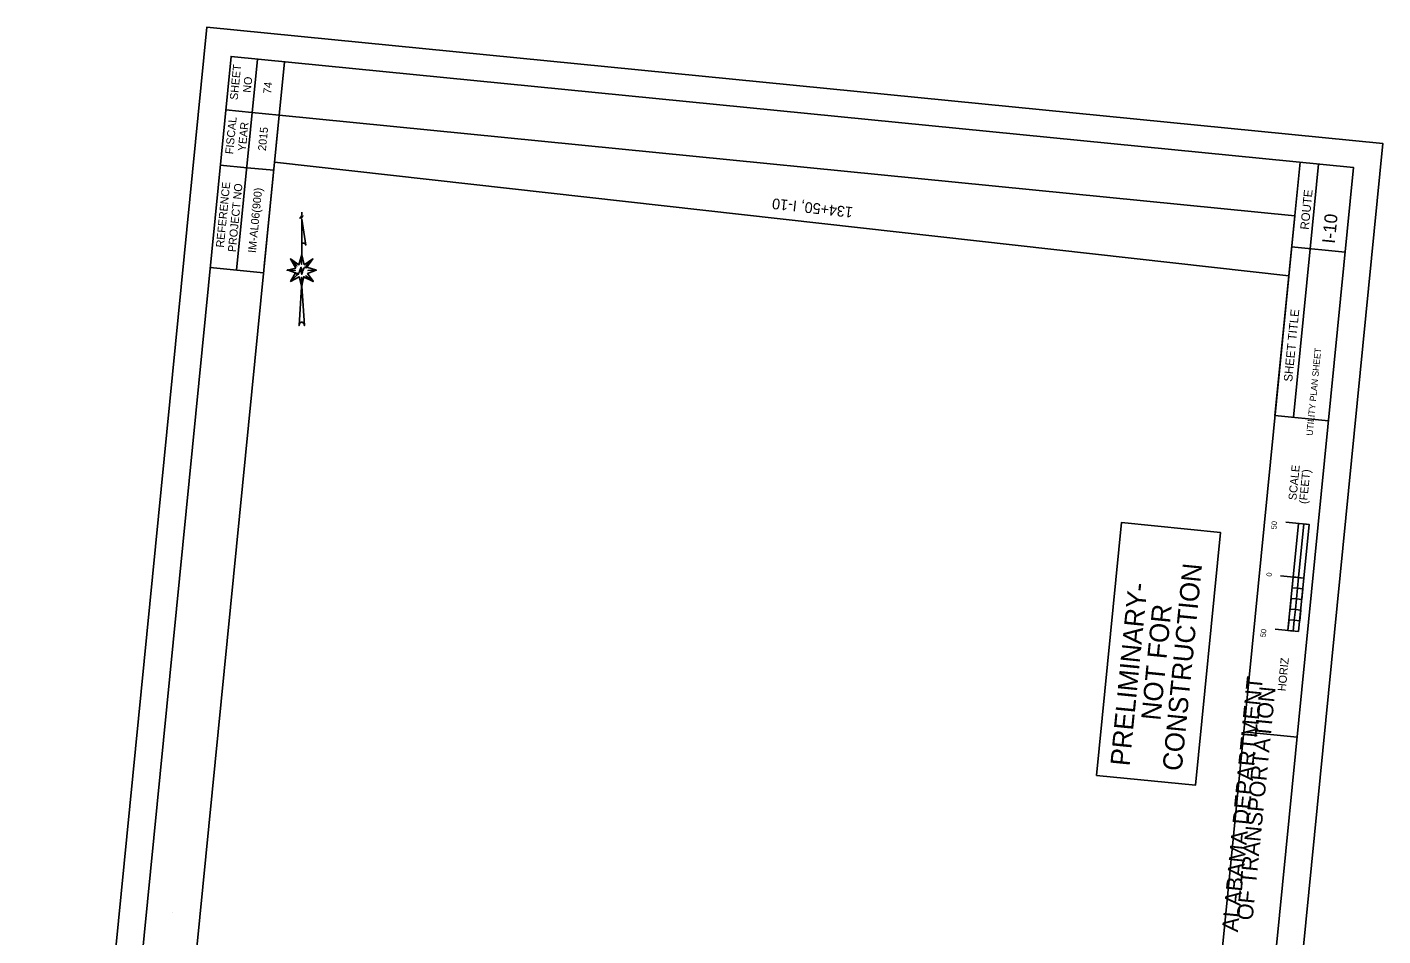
# Model space of a CAD drawing. Extents: x 1797076 to 1798338, y 246730 to 248530.
# Drawn here: x 1797076 to 1798338, y 247685 to 248530 of the extents above; entities that cross this region are included whole.
import ezdxf

# ---------------------------------------------------------------- set-up
doc = ezdxf.new("R2010")
doc.units = 0
for name, color, linetype in [('1', 7, 'Continuous'), ('29', 7, 'Continuous'), ('ANNO-SHT', 7, 'Continuous'), ('ANNO-SYMB', 7, 'Continuous'), ('ANNO-TXT', 7, 'Continuous'), ('DRAINAGE', 7, 'Continuous'), ('Level 1', 7, 'Continuous'), ('Level 57', 7, 'Continuous'), ('Level 6', 7, 'Continuous'), ('Level 62', 7, 'Continuous'), ('SHT-BDR', 7, 'Continuous'), ('SHT-BNDRY', 7, 'Continuous')]:
    doc.layers.add(name, color=color, linetype=linetype)

# ---------------------------------------------------------------- blocks, each defined once
blk = doc.blocks.new('SC47208')
at = {"layer": 'Level 1'}
blk.add_line((0, 0), (0, 0), dxfattribs=at)

msp = doc.modelspace()

# ---------------------------------------------------------------- linework, layer by layer
at = {"layer": '1'}
msp.add_lwpolyline([(1798071.6, 247833.9), (1798094.8, 248069.2), (1798187, 248060.1), (1798163.7, 247824.8)], close=True, dxfattribs=at)
at = {"layer": '29'}
msp.add_line((1797306.5, 248404.6), (1798250.6, 248298.9), dxfattribs=at)
at = {"layer": 'ANNO-SYMB'}
for p, q in [((1798269.7, 248067.4), (1798247.8, 248069.5)), ((1798259.7, 248068.3), (1798249.9, 247968.8)), ((1798269.7, 248067.4), (1798259.8, 247967.8)), ((1798269.7, 248067.4), (1798264.7, 248067.9)), ((1798269.7, 248067.4), (1798264.7, 248067.9)), ((1798269.7, 248067.4), (1798264.7, 248067.9)), ((1798264.7, 248017.6), (1798242.9, 248019.8)), ((1798264.7, 248017.6), (1798242.9, 248019.8)), ((1798264.7, 248017.6), (1798242.9, 248019.8)), ((1798259.8, 248018.1), (1798254.8, 248018.6)), ((1798259.8, 248018.1), (1798254.8, 248018.6)), ((1798259.8, 248018.1), (1798254.8, 248018.6)), ((1798259.8, 248018.1), (1798257.8, 247998.2)), ((1798259.8, 247967.8), (1798237.9, 247970)), ((1798255.8, 247978.3), (1798250.9, 247978.8)), ((1798255.8, 247978.3), (1798250.9, 247978.8))]:
    msp.add_line(p, q, dxfattribs=at)
for points in [[(1798259.8, 248018.1), (1798264.7, 248067.9), (1798269.7, 248067.4), (1798264.7, 248017.6)], [(1798253.8, 248008.6), (1798254.8, 248018.6), (1798259.8, 248018.1), (1798258.8, 248008.1)], [(1798257.8, 247998.2), (1798258.8, 248008.1), (1798263.8, 248007.7), (1798262.8, 247997.7)], [(1798251.8, 247988.7), (1798252.8, 247998.7), (1798257.8, 247998.2), (1798256.8, 247988.2)], [(1798255.8, 247978.3), (1798256.8, 247988.2), (1798261.8, 247987.7), (1798260.8, 247977.8)], [(1798249.9, 247968.8), (1798250.9, 247978.8), (1798255.8, 247978.3), (1798254.8, 247968.3)]]:
    msp.add_lwpolyline(points, close=True, dxfattribs=at)
at = {"layer": 'ANNO-TXT'}
for p, q in [((1798270.6, 248324.1), (1798278.4, 248402.8)), ((1798255.1, 248167.3), (1798270.6, 248324.1))]:
    msp.add_line(p, q, dxfattribs=at)
at = {"layer": 'Level 57'}
msp.add_line((1797331.9, 248358.2), (1797331.8, 248355.7), dxfattribs=at)
for points in [[(1797333, 248354.6), (1797332.9, 248354.6), (1797333, 248354.4), (1797333.1, 248354.6), (1797333, 248354.7), (1797332.8, 248354.7), (1797332.6, 248354.6), (1797332.4, 248354.5), (1797332.2, 248354.1), (1797332.1, 248353.7), (1797331.9, 248353.1), (1797331.8, 248353), (1797331.7, 248352.6), (1797331.7, 248353.2), (1797331.7, 248354.1), (1797331.5, 248354.7), (1797331.5, 248354.1), (1797331.7, 248352.6), (1797331.7, 248354.1), (1797331.5, 248354.7), (1797331.3, 248354.2), (1797330.9, 248353.1), (1797330.6, 248352.6), (1797330.4, 248352.5), (1797330.2, 248352.5), (1797330.1, 248352.6), (1797330.1, 248352.8), (1797330.2, 248352.9), (1797330.3, 248352.8), (1797330.2, 248352.7)], [(1797331.8, 248351.6), (1797335.5, 248327.5), (1797335.3, 248328.3), (1797335.1, 248328.6), (1797334.7, 248328.9), (1797334.2, 248329.2), (1797333.9, 248329.2), (1797333.5, 248329.2), (1797333.1, 248329.3), (1797332.8, 248329.1), (1797332.5, 248329), (1797332.2, 248328.7), (1797332, 248328.5), (1797331.9, 248328.2), (1797331.8, 248328), (1797331.8, 248351.5), (1797331.9, 248318.6)], [(1797331.9, 248318.6), (1797331.7, 248309.7), (1797331.9, 248318.7), (1797329.2, 248309.1), (1797321.3, 248314.6), (1797327.4, 248307.9), (1797321.3, 248314.6), (1797326.2, 248306.1), (1797318.2, 248304.1), (1797325.9, 248303.9), (1797318.3, 248304.3), (1797326.1, 248301.5), (1797321.5, 248293.6), (1797327.3, 248299.4), (1797321.5, 248293.6), (1797329.4, 248298), (1797331.7, 248289.1), (1797331.6, 248297.4), (1797331.7, 248288.9), (1797333.7, 248297.9), (1797342.7, 248293.7), (1797333.6, 248297.9), (1797331.7, 248288.6), (1797329.4, 248252.6), (1797329.6, 248253.8), (1797329.9, 248254.6), (1797330.4, 248255.1), (1797331, 248255.5), (1797331.5, 248255.6), (1797332.2, 248255.6), (1797332.7, 248255.4), (1797333.2, 248255.1), (1797333.6, 248254.6), (1797334, 248254), (1797334.1, 248253.5), (1797334.3, 248252.6), (1797331.8, 248289.1), (1797333.6, 248298), (1797342.5, 248293.7), (1797335.7, 248299), (1797342.4, 248293.9), (1797337.2, 248300.9), (1797345.2, 248304), (1797337.6, 248303.9), (1797345.5, 248304), (1797336.7, 248306.8), (1797342.2, 248314.6), (1797335.7, 248308.3), (1797342.2, 248314.6), (1797334.2, 248309.1), (1797332, 248318.5)], [(1797335.7, 248306.6), (1797335.5, 248306.4), (1797335.8, 248306.1), (1797336, 248306.5), (1797335.9, 248306.8), (1797335.8, 248307), (1797335.1, 248306.9), (1797334.5, 248306.6), (1797333.5, 248305.4), (1797333.4, 248304.9), (1797333, 248303.7), (1797332.6, 248302.5), (1797332.1, 248301.6), (1797331.9, 248300.2), (1797331.9, 248302), (1797331.7, 248304.2), (1797331.6, 248305.4), (1797331.1, 248306.8), (1797331.1, 248305.1), (1797331.4, 248302.9), (1797331.6, 248301.4), (1797331.9, 248300.3), (1797331.9, 248302.3), (1797331.7, 248305.4), (1797331.1, 248306.9), (1797330.8, 248305.4), (1797330.2, 248303.8), (1797329.9, 248303.1), (1797329.6, 248302.3), (1797329.2, 248301.5), (1797328.9, 248301), (1797328.7, 248300.4), (1797327.8, 248300.1), (1797327.2, 248300.2), (1797327, 248300.5), (1797326.9, 248301.2), (1797327.3, 248301.5), (1797327.6, 248301.1), (1797327.4, 248300.9)]]:
    msp.add_lwpolyline(points, dxfattribs=at)
at = {"layer": 'Level 6'}
for p, q in [((1797290.6, 248500.6), (1797271.2, 248304.2)), ((1797315.7, 248498.1), (1797296.9, 248307.8)), ((1797285.3, 248450.8), (1797261.1, 248453.2)), ((1797285.3, 248450.8), (1797310.8, 248448.3)), ((1797280.9, 248399.5), (1797256, 248402)), ((1797280.9, 248399.5), (1797305.7, 248397.1)), ((1798261.1, 248404.5), (1798237.8, 248169)), ((1797246.6, 248306.7), (1797296.3, 248301.7))]:
    msp.add_line(p, q, dxfattribs=at)
at = {"layer": 'Level 62'}
msp.add_lwpolyline([(1798170.8, 246730.3), (1798338.2, 248422), (1797243.6, 248530.3), (1797076.2, 246838.6)], close=True, dxfattribs=at)
at = {"layer": 'SHT-BDR'}
msp.add_lwpolyline([(1798108.5, 246862), (1798256.2, 248354.7), (1797310.8, 248448.3), (1797163.1, 246955.6)], close=True, dxfattribs=at)
at = {"layer": 'SHT-BNDRY'}
for p, q in [((1798303.1, 248320.9), (1798253.3, 248325.8)), ((1798287.6, 248164), (1798237.8, 248169)), ((1798258.5, 247869.5), (1798208.6, 247874.5))]:
    msp.add_line(p, q, dxfattribs=at)
msp.add_lwpolyline([(1798152.1, 246794.9), (1798310.9, 248399.6), (1797266, 248503), (1797107.2, 246898.3)], close=True, dxfattribs=at)

# ---------------------------------------------------------------- block references
at = {"layer": 'DRAINAGE', "xscale": 1.000002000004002, "yscale": 1.000002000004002, "rotation": -32.06753455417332}
msp.add_blockref('SC47208', (1797211.3, 247706.1), dxfattribs=at)
msp.add_blockref('SC47208', (1797211.3, 247706.1), dxfattribs=at)

# ---------------------------------------------------------------- texts
at = {"layer": '1'}
for s, p in [('CONSTRUCTION', (1798150.9, 247837.4)), ('PRELIMINARY-', (1798102.4, 247842.1)), ('NOT FOR', (1798131.1, 247884.5))]:
    msp.add_text(s, height=18, rotation=84.3491, dxfattribs=at).set_placement(p)
at = {"layer": 'ANNO-SHT'}
for s, height, rotation, p in [('74', 7.45, 84.3491, (1797303.3, 248467.9)), ('2015', 7.45, 84.3491, (1797298.4, 248414.9)), ('IM-AL06(900)', 7.449, 84.3491, (1797289.1, 248319.9)), ('134+50, I-10', 10, 173.6129, (1797845.3, 248362.7)), ('  I-10  ', 12, 84.3491, (1798292.6, 248319.6)), ('           UTILITY PLAN SHEET           ', 6, 84.3491, (1798270.4, 248125.4))]:
    msp.add_text(s, height=height, rotation=rotation, dxfattribs=at).set_placement(p)
at = {"layer": 'ANNO-SYMB'}
for s, height, p in [('SCALE', 7.5, (1798257.7, 248089.8)), ('(FEET)', 7.5, (1798267.6, 248086.3)), (' 50', 5, (1798238.9, 248060.8)), ('0', 5, (1798234.7, 248018.7)), ('0', 5, (1798234.7, 248018.7)), ('0', 5, (1798234.7, 248018.7)), (' 50', 5, (1798228.9, 247960.4)), ('HORIZ', 7.5, (1798247.7, 247912))]:
    msp.add_text(s, height=height, rotation=84.4063, dxfattribs=at).set_placement(p)
at = {"layer": 'ANNO-TXT'}
for s, height, p in [('ROUTE', 8, (1798269.2, 248341.5)), ('SHEET TITLE', 8, (1798253.8, 248200)), ('ALABAMA DEPARTMENT', 15, (1798203.2, 247687.7)), ('OF TRANSPORTATION', 15, (1798216.9, 247698.5))]:
    msp.add_text(s, height=height, rotation=84.3491, dxfattribs=at).set_placement(p)
at = {"layer": 'Level 6'}
for s, p in [('SHEET', (1797272.2, 248462.3)), ('NO', (1797284.4, 248469)), ('FISCAL', (1797267.9, 248411.8)), ('YEAR', (1797279.7, 248414.6)), ('REFERENCE', (1797259.3, 248324.9)), ('PROJECT NO', (1797270.4, 248320.7))]:
    msp.add_text(s, height=7.44, rotation=84.3491, dxfattribs=at).set_placement(p)

doc.saveas('drawing.dxf')
